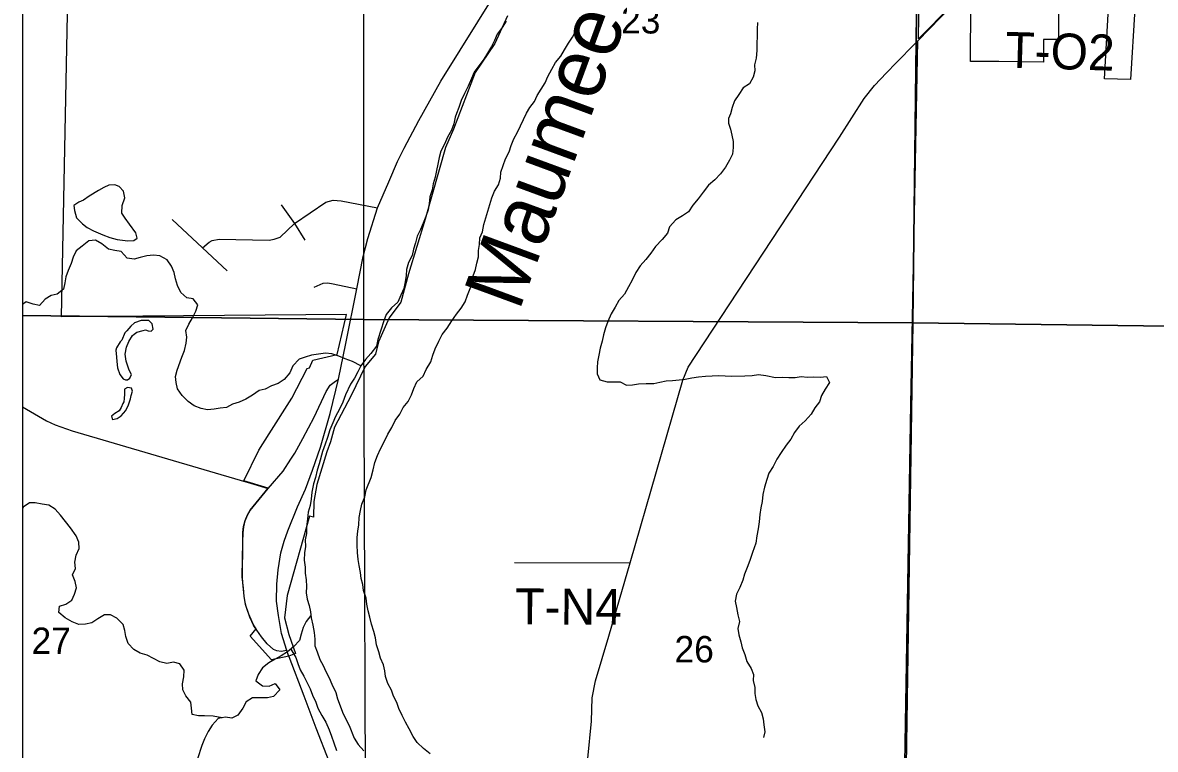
# Model space of a CAD drawing. Extents: x -6.2 to 37.4, y 0.2 to 22.2.
# Drawn here: x 1.681 to 2.577, y 16.05 to 16.626 of the extents above; entities that cross this region are included whole.
import ezdxf

# ---------------------------------------------------------------- set-up
doc = ezdxf.new("R2010")
doc.units = 0
for name, color, linetype in [('GM_X_City_Street', 7, 'Continuous'), ('GM_X_Corporation', 7, 'Continuous'), ('GM_X_County_Road', 7, 'Continuous'), ('GM_X_Major_River', 7, 'Continuous'), ('GM_X_Major_River_Text', 7, 'Continuous'), ('GM_X_Minor_Lake', 7, 'Continuous'), ('GM_X_Minor_River', 7, 'Continuous'), ('GM_X_Rail_Line', 7, 'Continuous'), ('GM_X_Section', 7, 'Continuous'), ('GM_X_Section_Text', 7, 'Continuous'), ('GM_X_Township_Road', 7, 'Continuous'), ('GM_X_Township_Road_Text', 7, 'Continuous'), ('GM_X_US_Shield', 7, 'Continuous'), ('SH_Cut_Line', 7, 'Continuous'), ('SH_Data', 7, 'Continuous')]:
    doc.layers.add(name, color=color, linetype=linetype)

msp = doc.modelspace()

# ---------------------------------------------------------------- linework, layer by layer
at = {"layer": 'GM_X_City_Street'}
for points in [[(1.8232, 16.44762), (1.8285, 16.45197), (1.83099, 16.45327), (1.83652, 16.45433), (1.87602, 16.45359), (1.88002, 16.4543), (1.88479, 16.45594), (1.89592, 16.46684), (1.9208, 16.48366), (1.92662, 16.4852), (1.93286, 16.48478), (1.96185, 16.4792)], [(1.8854, 16.48156), (1.89592, 16.46684), (1.90419, 16.45359)], [(1.79932, 16.46984), (1.8232, 16.44762), (1.8428, 16.42937)], [(1.91162, 16.41642), (1.9187, 16.41952), (1.92248, 16.41973), (1.92655, 16.41903), (1.9454, 16.41497)], [(1.87531, 16.2569), (1.88708, 16.27064), (1.89325, 16.2801), (1.8962, 16.2848), (1.90272, 16.29658), (1.91169, 16.31354), (1.92101, 16.33373), (1.92423, 16.33863), (1.92753, 16.3411), (1.93075, 16.3434)]]:
    msp.add_lwpolyline(points, dxfattribs=at)
at = {"layer": 'GM_X_Corporation'}
for points in [[(2.4164, 16.63969), (2.38997, 16.61316), (2.39224, 16.77554)], [(2.0646, 16.63133), (2.05451, 16.60928), (2.03907, 16.58637), (2.0219, 16.54164), (2.0156, 16.5269), (1.99955, 16.47029), (1.98635, 16.42695), (1.98013, 16.40442), (1.971, 16.392), (1.96261, 16.37296), (1.96023, 16.36343), (1.95191, 16.35351), (1.94082, 16.3305), (1.92776, 16.3055), (1.92459, 16.294), (1.92177, 16.28598), (1.91385, 16.25999), (1.91144, 16.24664), (1.91112, 16.23413), (1.90793, 16.235), (1.89021, 16.17225), (1.88807, 16.15457), (1.89169, 16.14128), (1.89686, 16.12615), (1.8916, 16.1241), (1.87785, 16.12111), (1.86103, 16.13991), (1.86565, 16.14589), (1.86349, 16.14895), (1.85977, 16.15749), (1.85737, 16.16504), (1.85615, 16.1717), (1.85505, 16.18258), (1.85474, 16.18699), (1.85516, 16.2148), (1.85523, 16.22195), (1.85578, 16.22693), (1.85694, 16.23151), (1.85878, 16.23602), (1.86088, 16.23972), (1.87519, 16.25718), (1.85589, 16.26304), (1.86788, 16.2874), (1.87604, 16.30018), (1.89401, 16.32849), (1.90597, 16.35191), (1.90782, 16.35253), (1.91058, 16.35846), (1.9299, 16.36294), (1.93729, 16.39482), (1.71166, 16.39298), (1.71731, 16.68614)], [(2.50084, 16.63835), (2.50076, 16.61249), (2.48898, 16.61242), (2.48891, 16.59469), (2.45347, 16.59518), (2.44367, 16.59508), (2.43124, 16.59515), (2.43138, 16.64023)], [(2.56127, 16.63675), (2.55794, 16.58078), (2.53712, 16.58129), (2.54044, 16.63725)]]:
    msp.add_lwpolyline(points, dxfattribs=at)
at = {"layer": 'GM_X_County_Road'}
for p, q in [((2.3895, 16.61161), (2.41652, 16.63941)), ((2.38743, 16.6095), (2.3895, 16.61161)), ((1.86124, 16.26118), (1.87531, 16.2569))]:
    msp.add_line(p, q, dxfattribs=at)
for points in [[(1.89179, 16.12364), (1.89108, 16.12551), (1.88996, 16.12856), (1.88589, 16.14202), (1.8833, 16.15632), (1.8819, 16.16774), (1.88197, 16.18113), (1.88302, 16.19262), (1.88526, 16.20587), (1.88799, 16.21527), (1.89088, 16.22336), (1.89844, 16.24238), (1.90478, 16.25629), (1.91022, 16.27141), (1.91652, 16.28964), (1.92437, 16.31641), (1.93075, 16.3434), (1.93678, 16.37165), (1.9454, 16.41497), (1.95052, 16.44055), (1.95417, 16.45499), (1.96185, 16.4792), (1.97085, 16.49985), (1.97749, 16.51597), (1.98283, 16.52656), (1.99454, 16.54836), (2.01192, 16.57962), (2.0565, 16.65126)], [(2.17886, 15.77135), (2.17423, 15.79416), (2.15735, 15.83754), (2.13664, 15.8739), (2.12213, 15.89714), (2.11897, 15.90931), (2.11849, 15.92697), (2.12203, 16.02247), (2.12359, 16.03044), (2.12822, 16.04296), (2.13103, 16.07276), (2.1317, 16.09117), (2.13443, 16.10446), (2.14488, 16.13992), (2.16169, 16.19805), (2.20351, 16.34266), (2.20755, 16.35308), (2.21368, 16.36217), (2.32755, 16.53511), (2.34687, 16.56576), (2.35511, 16.57606), (2.36464, 16.58624), (2.37224, 16.59399), (2.38743, 16.6095)], [(2.3744, 15.3797), (2.37573, 15.63221), (2.37619, 15.75431), (2.37666, 15.88116), (2.38391, 16.32379), (2.3895, 16.61161)], [(1.68086, 16.32152), (1.69983, 16.31059), (1.70665, 16.30733), (1.72011, 16.30271), (1.85749, 16.26232), (1.86124, 16.26118)], [(1.86445, 16.14741), (1.8636, 16.14868), (1.86074, 16.15511), (1.85808, 16.16257), (1.85697, 16.16697), (1.85627, 16.17142), (1.85557, 16.17829), (1.85517, 16.18231), (1.85485, 16.18672), (1.85527, 16.21452), (1.85534, 16.22168), (1.8559, 16.22666), (1.85706, 16.23124), (1.85889, 16.23575), (1.861, 16.23945), (1.87531, 16.2569)], [(1.88996, 16.12856), (1.88561, 16.12779), (1.88198, 16.12823), (1.87944, 16.12947), (1.87433, 16.13395), (1.86984, 16.13942), (1.86445, 16.14741)], [(1.92346, 16.04076), (1.91333, 16.06715), (1.90363, 16.09239), (1.89179, 16.12364)]]:
    msp.add_lwpolyline(points, dxfattribs=at)
at = {"layer": 'GM_X_Major_River'}
for points in [[(2.0637, 16.62706), (2.06051, 16.62204), (2.05635, 16.61666), (2.0543, 16.61179), (2.05187, 16.60693), (2.04886, 16.60171), (2.04586, 16.59687), (2.0419, 16.59168), (2.03833, 16.58666), (2.03608, 16.58161), (2.03343, 16.57562), (2.03059, 16.56982), (2.02794, 16.56421), (2.02625, 16.55857), (2.02436, 16.55395)], [(2.07963, 16.5543), (2.08225, 16.5588), (2.08597, 16.56339), (2.08821, 16.56825), (2.09121, 16.57309), (2.0946, 16.5783), (2.09665, 16.58336), (2.09987, 16.58896), (2.10269, 16.59437), (2.10684, 16.59937), (2.10965, 16.60441), (2.11304, 16.60962), (2.11623, 16.61445), (2.11886, 16.6195), (2.12243, 16.6247), (2.12449, 16.62957)], [(2.02436, 16.55395), (2.02327, 16.55098), (2.02205, 16.54587), (2.02025, 16.54077), (2.01713, 16.53512), (2.01476, 16.52966), (2.01201, 16.52419), (2.0106, 16.51909), (2.00956, 16.51379), (2.00834, 16.50887), (2.0073, 16.50357), (2.00588, 16.49828), (2.00504, 16.49336), (2.00305, 16.48788), (2.00259, 16.48276), (2.00174, 16.47765), (2.00013, 16.47236), (1.99777, 16.46708), (1.99579, 16.46199), (1.99323, 16.45671), (1.99182, 16.45161), (1.99022, 16.44651), (1.98918, 16.4414), (1.98624, 16.43594), (1.98482, 16.43045), (1.98455, 16.42552), (1.98371, 16.4206), (1.98267, 16.4153), (1.98031, 16.41002), (1.97794, 16.40455), (1.97293, 16.39988), (1.96867, 16.39463), (1.96669, 16.38973), (1.96189, 16.375), (1.96085, 16.3697), (1.95658, 16.36388), (1.95214, 16.35901), (1.94845, 16.35413), (1.9461, 16.34923), (1.94355, 16.34433), (1.94043, 16.33944), (1.9365, 16.33115)], [(2.0035, 16.04674), (1.99808, 16.051), (1.99304, 16.05563), (1.99008, 16.06042), (1.98678, 16.06655), (1.98402, 16.0719), (1.98127, 16.07707), (1.97871, 16.08261), (1.97709, 16.08738), (1.97452, 16.09255), (1.97282, 16.09731), (1.96995, 16.10249), (1.96819, 16.10803), (1.96766, 16.11258), (1.96641, 16.11735), (1.96423, 16.1225), (1.96279, 16.12746), (1.96099, 16.13318), (1.96014, 16.13851), (1.9589, 16.14365), (1.95691, 16.14957), (1.95568, 16.1549), (1.95444, 16.16005), (1.95339, 16.16519), (1.95273, 16.1701), (1.95073, 16.17605), (1.95006, 16.18099), (1.94881, 16.18576), (1.94832, 16.19051), (1.94728, 16.19584), (1.94641, 16.2006), (1.94594, 16.2063), (1.94566, 16.212), (1.94576, 16.21807), (1.94622, 16.223), (1.94688, 16.22811), (1.94736, 16.23399), (1.94821, 16.23948), (1.94943, 16.2444), (1.95162, 16.25044), (1.95285, 16.25574), (1.9568, 16.26555), (1.95842, 16.2716), (1.95966, 16.27746), (1.96184, 16.28313), (1.96401, 16.28822), (1.96714, 16.29386), (1.9699, 16.2999), (1.97303, 16.30535), (1.97577, 16.31082), (1.97946, 16.31589), (1.9822, 16.32097), (1.98607, 16.32585), (1.98863, 16.33112), (1.99042, 16.33622), (1.99297, 16.34131), (1.99779, 16.34579), (2.00034, 16.35107), (2.00405, 16.35727), (2.00566, 16.36256), (2.00745, 16.36747), (2.01021, 16.37369), (2.01295, 16.37897), (2.01701, 16.38384), (2.02052, 16.38967), (2.02422, 16.39493), (2.02809, 16.39981), (2.03102, 16.4047), (2.03301, 16.41017), (2.03499, 16.41527), (2.03717, 16.42074), (2.03744, 16.42548), (2.03942, 16.43039), (2.04026, 16.43531), (2.04167, 16.44041), (2.04176, 16.44535), (2.04241, 16.45027), (2.04268, 16.45539), (2.04485, 16.4603), (2.0459, 16.46597), (2.05072, 16.48185), (2.05232, 16.48714), (2.05431, 16.49242), (2.05743, 16.49731), (2.05903, 16.5026), (2.0593, 16.50734), (2.06129, 16.51282), (2.06309, 16.5181), (2.06602, 16.52356), (2.06744, 16.52867), (2.0698, 16.53376), (2.07255, 16.53922), (2.0749, 16.54412), (2.07963, 16.5543)], [(1.9365, 16.33115), (1.93432, 16.3253), (1.93157, 16.31965), (1.92844, 16.314), (1.92645, 16.30891), (1.9239, 16.30344), (1.92209, 16.29739), (1.92029, 16.29211), (1.9183, 16.28625), (1.91548, 16.27642), (1.91387, 16.27132), (1.91264, 16.26565), (1.91122, 16.26054), (1.90979, 16.25411), (1.90912, 16.24843), (1.90847, 16.2435), (1.90686, 16.23821), (1.90639, 16.2329), (1.90553, 16.22665), (1.90544, 16.22134), (1.90461, 16.21628), (1.90469, 16.21091), (1.90404, 16.20599), (1.90375, 16.20011), (1.90441, 16.19459), (1.90454, 16.18978), (1.90538, 16.18452), (1.90567, 16.17939), (1.90521, 16.17427)], [(1.90521, 16.17427), (1.90607, 16.16913), (1.90769, 16.16417), (1.90874, 16.15922), (1.90923, 16.15447), (1.91046, 16.14875), (1.91149, 16.14285), (1.91216, 16.13753), (1.91226, 16.13221), (1.91408, 16.12744), (1.91606, 16.12152), (1.91882, 16.11674), (1.92083, 16.11196), (1.9234, 16.10699), (1.92558, 16.10202), (1.92869, 16.09533), (1.93013, 16.09037), (1.93212, 16.08484), (1.93412, 16.07987), (1.9363, 16.07471), (1.93924, 16.06916), (1.94324, 16.05923), (1.94657, 16.05425), (1.95084, 16.04906)]]:
    msp.add_lwpolyline(points, dxfattribs=at)
at = {"layer": 'GM_X_Minor_Lake'}
for p, q in [((1.74079, 16.49299), (1.73351, 16.48854)), ((1.7618, 16.38011), (1.75924, 16.37446)), ((1.76087, 16.32546), (1.76009, 16.32414))]:
    msp.add_line(p, q, dxfattribs=at)
for points in [[(1.73351, 16.48854), (1.7289, 16.48539), (1.72527, 16.48373), (1.72125, 16.48095), (1.72194, 16.47714), (1.72355, 16.47142), (1.7282, 16.46642), (1.73195, 16.4637), (1.73702, 16.46097), (1.74436, 16.45782), (1.74982, 16.45584), (1.75567, 16.45423), (1.76399, 16.45297), (1.76892, 16.45327), (1.77142, 16.45513), (1.77055, 16.45951), (1.76535, 16.46623), (1.76202, 16.47103), (1.75925, 16.47506), (1.75954, 16.48113), (1.76173, 16.48717), (1.76068, 16.4925), (1.75733, 16.49616), (1.75394, 16.49754), (1.7492, 16.49704), (1.745, 16.49539), (1.74079, 16.49299)], [(1.75924, 16.37446), (1.75808, 16.37295), (1.75516, 16.36844), (1.75455, 16.36636), (1.75503, 16.36104), (1.75554, 16.35762), (1.75602, 16.35249), (1.75783, 16.34733), (1.76043, 16.34388), (1.76231, 16.3429), (1.76382, 16.34288), (1.76574, 16.34437), (1.76693, 16.3472), (1.76509, 16.35064), (1.76275, 16.3577), (1.7619, 16.36341), (1.76313, 16.36889), (1.76491, 16.37342), (1.76783, 16.37812), (1.76918, 16.37924), (1.77129, 16.38073), (1.77624, 16.38217), (1.77815, 16.38252), (1.78022, 16.38192), (1.78249, 16.38151), (1.78422, 16.38319), (1.78335, 16.38738), (1.78074, 16.39007), (1.77467, 16.38998), (1.76952, 16.38816), (1.76644, 16.38536), (1.76335, 16.3818), (1.7618, 16.38011)], [(1.76009, 16.32414), (1.7589, 16.32112), (1.75734, 16.31849), (1.7537, 16.31627), (1.7512, 16.31422), (1.75191, 16.31155), (1.75572, 16.31244), (1.75879, 16.31448), (1.76246, 16.3186), (1.76463, 16.32331), (1.76622, 16.32803), (1.76683, 16.33049), (1.76784, 16.33408), (1.76693, 16.33638), (1.76391, 16.33699), (1.76142, 16.3357), (1.76135, 16.33152), (1.7613, 16.3283), (1.76087, 16.32546)]]:
    msp.add_lwpolyline(points, dxfattribs=at)
at = {"layer": 'GM_X_Minor_River'}
for points in [[(2.26248, 16.62592), (2.26231, 16.62081), (2.26232, 16.61511), (2.26195, 16.60924), (2.26196, 16.60374), (2.26159, 16.59787), (2.26028, 16.5924), (2.26051, 16.58765), (2.25902, 16.58258), (2.2562, 16.57754), (2.25117, 16.57428), (2.24777, 16.56888), (2.24439, 16.56405), (2.24251, 16.5586), (2.24122, 16.55371), (2.23959, 16.54996)], [(2.23959, 16.54996), (2.23948, 16.54638), (2.2413, 16.5416), (2.24235, 16.53684), (2.24321, 16.5317), (2.24332, 16.52696), (2.24267, 16.52184), (2.2405, 16.51694), (2.23718, 16.51148), (2.2333, 16.50623), (2.22886, 16.50136), (2.22386, 16.49726), (2.21959, 16.49163), (2.21571, 16.48637), (2.21146, 16.48131), (2.20795, 16.47605), (2.20316, 16.4729), (2.19799, 16.46975), (2.19278, 16.46413), (2.19118, 16.45922), (2.18711, 16.45416), (2.18171, 16.44854), (2.1782, 16.44328), (2.17414, 16.43841), (2.16969, 16.43335), (2.16619, 16.42809), (2.16324, 16.42187), (2.16031, 16.4166), (2.15718, 16.41095), (2.15273, 16.4057), (2.1498, 16.40043), (2.14668, 16.39536), (2.14411, 16.38913), (2.14213, 16.38423), (2.14071, 16.37855), (2.13948, 16.37364), (2.13806, 16.36815), (2.13683, 16.36248), (2.13598, 16.35718), (2.13571, 16.35243), (2.13563, 16.34769), (2.13763, 16.34291), (2.14349, 16.3415), (2.15372, 16.34134), (2.15879, 16.3388), (2.16354, 16.33892), (2.16848, 16.33979), (2.17455, 16.34008), (2.18042, 16.33999), (2.18537, 16.34124), (2.19013, 16.34212), (2.19525, 16.34242), (2.20057, 16.34291), (2.20532, 16.3436), (2.21045, 16.34466), (2.21596, 16.34534), (2.22128, 16.34583), (2.22659, 16.34612), (2.23172, 16.34643), (2.23702, 16.34616), (2.24232, 16.34589), (2.25256, 16.34611), (2.25844, 16.3464), (2.26339, 16.34727), (2.26906, 16.34643), (2.2768, 16.34479), (2.28231, 16.34509), (2.28723, 16.34483), (2.29235, 16.34494), (2.2971, 16.34563), (2.30202, 16.34517), (2.30695, 16.34548), (2.31245, 16.3452), (2.31719, 16.3457), (2.31958, 16.34092), (2.31608, 16.33566), (2.31334, 16.33057), (2.31155, 16.32567), (2.30805, 16.32078), (2.30512, 16.3157), (2.30029, 16.31046), (2.29548, 16.30617), (2.2918, 16.30129), (2.28886, 16.29602), (2.28518, 16.29114), (2.28129, 16.2855), (2.27798, 16.28005), (2.27484, 16.27421), (2.27153, 16.26914), (2.26993, 16.26404), (2.26812, 16.25799), (2.26688, 16.25212), (2.26622, 16.24663), (2.26519, 16.24152), (2.26453, 16.23641), (2.26386, 16.23053), (2.2632, 16.22504), (2.26197, 16.21936), (2.26111, 16.21368), (2.25871, 16.20631), (2.25672, 16.20065)], [(1.94845, 16.35413), (1.94188, 16.35745), (1.93604, 16.35963), (1.93114, 16.3616), (1.92568, 16.36358), (1.92057, 16.36423), (1.90955, 16.3625), (1.90441, 16.36106), (1.89964, 16.35923), (1.89481, 16.35418), (1.89225, 16.34852), (1.8878, 16.34328), (1.88301, 16.34012), (1.87786, 16.33811), (1.87288, 16.33553), (1.86813, 16.33446), (1.86275, 16.33075), (1.85758, 16.3276), (1.85224, 16.32521), (1.84709, 16.32358), (1.84212, 16.32119), (1.83718, 16.32051), (1.83243, 16.31963), (1.8273, 16.31933), (1.8222, 16.32035), (1.81674, 16.32233), (1.81187, 16.32583), (1.80702, 16.33045), (1.80332, 16.33582), (1.80227, 16.34078), (1.80178, 16.34572), (1.80319, 16.35063), (1.80678, 16.36083), (1.80896, 16.3663), (1.81019, 16.37198), (1.81084, 16.3769), (1.80998, 16.38204), (1.81234, 16.38694), (1.81527, 16.39202), (1.81783, 16.3973), (1.81962, 16.40239), (1.81591, 16.40719), (1.8108, 16.40803), (1.80595, 16.41228), (1.80339, 16.41763), (1.80196, 16.42297), (1.80072, 16.42811), (1.79872, 16.43308), (1.7952, 16.43807), (1.78957, 16.44119), (1.78446, 16.44184), (1.77914, 16.44116), (1.774, 16.43991), (1.76905, 16.43847), (1.76357, 16.43931), (1.75873, 16.4445), (1.75381, 16.44534), (1.74871, 16.44637), (1.74367, 16.45081), (1.73841, 16.45373), (1.73328, 16.45305), (1.72809, 16.44895), (1.72329, 16.44523), (1.72093, 16.44014), (1.71914, 16.43504), (1.71696, 16.42957), (1.71498, 16.42467), (1.71433, 16.41974), (1.71311, 16.41483), (1.7083, 16.41072), (1.70335, 16.40966), (1.69857, 16.40688), (1.69412, 16.40183), (1.68921, 16.40304), (1.68374, 16.40483), (1.68086, 16.40271)], [(1.83875, 16.07529), (1.8317, 16.07649), (1.82469, 16.07678), (1.81995, 16.07685), (1.81504, 16.07788), (1.81456, 16.08282), (1.81388, 16.08758), (1.80998, 16.09257), (1.8076, 16.09754), (1.8073, 16.10229), (1.80835, 16.10778), (1.80882, 16.11309), (1.8053, 16.11808), (1.8002, 16.11929), (1.79507, 16.11842), (1.7894, 16.11965), (1.78433, 16.12219), (1.77945, 16.12492), (1.77398, 16.12652), (1.76891, 16.12945), (1.76444, 16.13426), (1.76245, 16.1396), (1.76177, 16.14436), (1.76033, 16.14913), (1.7553, 16.15414), (1.75042, 16.15687), (1.74568, 16.15675), (1.74032, 16.15361), (1.73553, 16.15064), (1.73058, 16.14958), (1.72545, 16.14909), (1.71999, 16.15126), (1.71455, 16.15457), (1.70951, 16.15882), (1.70997, 16.16375), (1.71511, 16.16538), (1.7199, 16.16834), (1.72188, 16.17325), (1.72348, 16.17816), (1.72243, 16.1833), (1.72044, 16.18845), (1.72261, 16.19355), (1.72212, 16.19849), (1.72316, 16.20398), (1.72553, 16.20945), (1.72543, 16.21438), (1.72324, 16.21935), (1.71861, 16.22588), (1.71471, 16.23087), (1.71081, 16.23567), (1.70654, 16.24048), (1.70147, 16.2436), (1.69637, 16.24462), (1.69089, 16.24566), (1.68615, 16.24554), (1.68116, 16.2422), (1.68086, 16.24145)], [(2.25672, 16.20065), (2.25493, 16.19574), (2.25216, 16.18914), (2.25094, 16.18422), (2.24857, 16.17856), (2.24602, 16.17329), (2.24479, 16.1678), (2.24602, 16.16266), (2.24688, 16.15695), (2.2483, 16.15161), (2.24688, 16.14594), (2.24774, 16.14099), (2.24935, 16.13546), (2.25041, 16.1307), (2.25241, 16.12555), (2.25402, 16.12002), (2.25752, 16.11427), (2.25934, 16.1095), (2.25925, 16.10475), (2.26049, 16.09942), (2.26041, 16.09467), (2.26128, 16.08992), (2.2629, 16.08477), (2.26565, 16.07941), (2.26708, 16.07445), (2.26757, 16.0697), (2.26823, 16.06419), (2.2674, 16.05964)], [(1.90903, 16.15644), (1.9052, 16.15168), (1.90284, 16.14678), (1.90124, 16.14149), (1.90001, 16.13657), (1.89557, 16.13171), (1.89057, 16.12742), (1.8854, 16.12446), (1.88062, 16.12168), (1.87564, 16.11872), (1.87064, 16.11481), (1.86733, 16.10954), (1.86554, 16.10445), (1.87078, 16.10057), (1.87589, 16.1003), (1.88086, 16.10251), (1.88437, 16.09733), (1.87936, 16.09228), (1.8746, 16.09121), (1.86284, 16.09101), (1.85786, 16.08805), (1.85512, 16.08297), (1.85124, 16.07733), (1.84646, 16.07512), (1.84135, 16.07577), (1.83565, 16.07472), (1.83082, 16.06948), (1.8277, 16.0644), (1.82476, 16.05875), (1.82259, 16.05347), (1.81937, 16.04289)], [(1.89318, 16.12966), (1.89713, 16.12314), (1.89875, 16.11818), (1.90057, 16.11341), (1.90351, 16.10824), (1.90571, 16.10346), (1.90846, 16.09829), (1.91027, 16.09333), (1.91302, 16.08778), (1.91446, 16.08302), (1.91758, 16.07709), (1.9209, 16.07191), (1.92345, 16.0658), (1.92526, 16.06065), (1.92726, 16.05549), (1.92924, 16.04938)]]:
    msp.add_lwpolyline(points, dxfattribs=at)
at = {"layer": 'GM_X_Rail_Line'}
msp.add_lwpolyline([(1.68086, 18.39138), (1.68086, 15.3872)], dxfattribs=at)
at = {"layer": 'GM_X_Section'}
for points in [[(2.46132, 16.87779), (2.64683, 16.88866), (2.90372, 16.88668), (2.89317, 16.38663), (2.89289, 16.38152), (2.38563, 16.38809), (2.38968, 16.74498), (2.46127, 16.86472)], [(1.96929, 16.87904), (2.46132, 16.87779), (2.46127, 16.86472), (2.38968, 16.74498), (2.38563, 16.38809), (1.95104, 16.39075), (1.95103, 16.64196)], [(2.38563, 16.38809), (2.37779, 15.87968), (1.95281, 15.87951), (1.95104, 16.39075)], [(2.38563, 16.38809), (2.89289, 16.38152), (2.88369, 15.88338), (2.88344, 15.87997), (2.37779, 15.87968)]]:
    msp.add_lwpolyline(points, close=True, dxfattribs=at)
at = {"layer": 'GM_X_Township_Road'}
msp.add_line((2.07025, 16.19822), (2.16169, 16.19805), dxfattribs=at)
at = {"layer": 'GM_X_US_Shield'}
for points in [[(1.68086, 16.89117), (1.68086, 16.39384), (1.95104, 16.39075), (1.95103, 16.64196), (1.96929, 16.87904)], [(1.68086, 16.39384), (1.68086, 15.89387), (1.95281, 15.87951), (1.95104, 16.39075)]]:
    msp.add_lwpolyline(points, close=True, dxfattribs=at)
at = {"layer": 'SH_Cut_Line'}
msp.add_lwpolyline([(1.68086, 20.39726), (1.68086, 14.30742)], dxfattribs=at)
at = {"layer": 'SH_Data'}
msp.add_line((1.68086, 21.10742), (1.68086, 14.30742), dxfattribs=at)

# ---------------------------------------------------------------- texts
at = {"layer": 'GM_X_Major_River_Text'}
msp.add_text('Maumee', height=0.047383, rotation=69.77352, dxfattribs=at).set_placement((2.07377, 16.39663))
at = {"layer": 'GM_X_Section_Text'}
for s, p in [('23', (2.15457, 16.61729)), ('27', (1.6879, 16.12583)), ('26', (2.19686, 16.11916))]:
    msp.add_text(s, height=0.020928, rotation=0.00001, dxfattribs=at).set_placement(p)
at = {"layer": 'GM_X_Township_Road_Text'}
for s, rotation, p in [('T-O2', 358.41851, (2.45841, 16.59021)), ('T-N4', 359.68362, (2.07075, 16.14941))]:
    msp.add_text(s, height=0.028409, rotation=rotation, dxfattribs=at).set_placement(p)

doc.saveas('drawing.dxf')
